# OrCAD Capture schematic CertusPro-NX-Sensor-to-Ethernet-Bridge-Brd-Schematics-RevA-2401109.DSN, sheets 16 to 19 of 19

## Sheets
16 Clock Synthesizer For Camera: size B
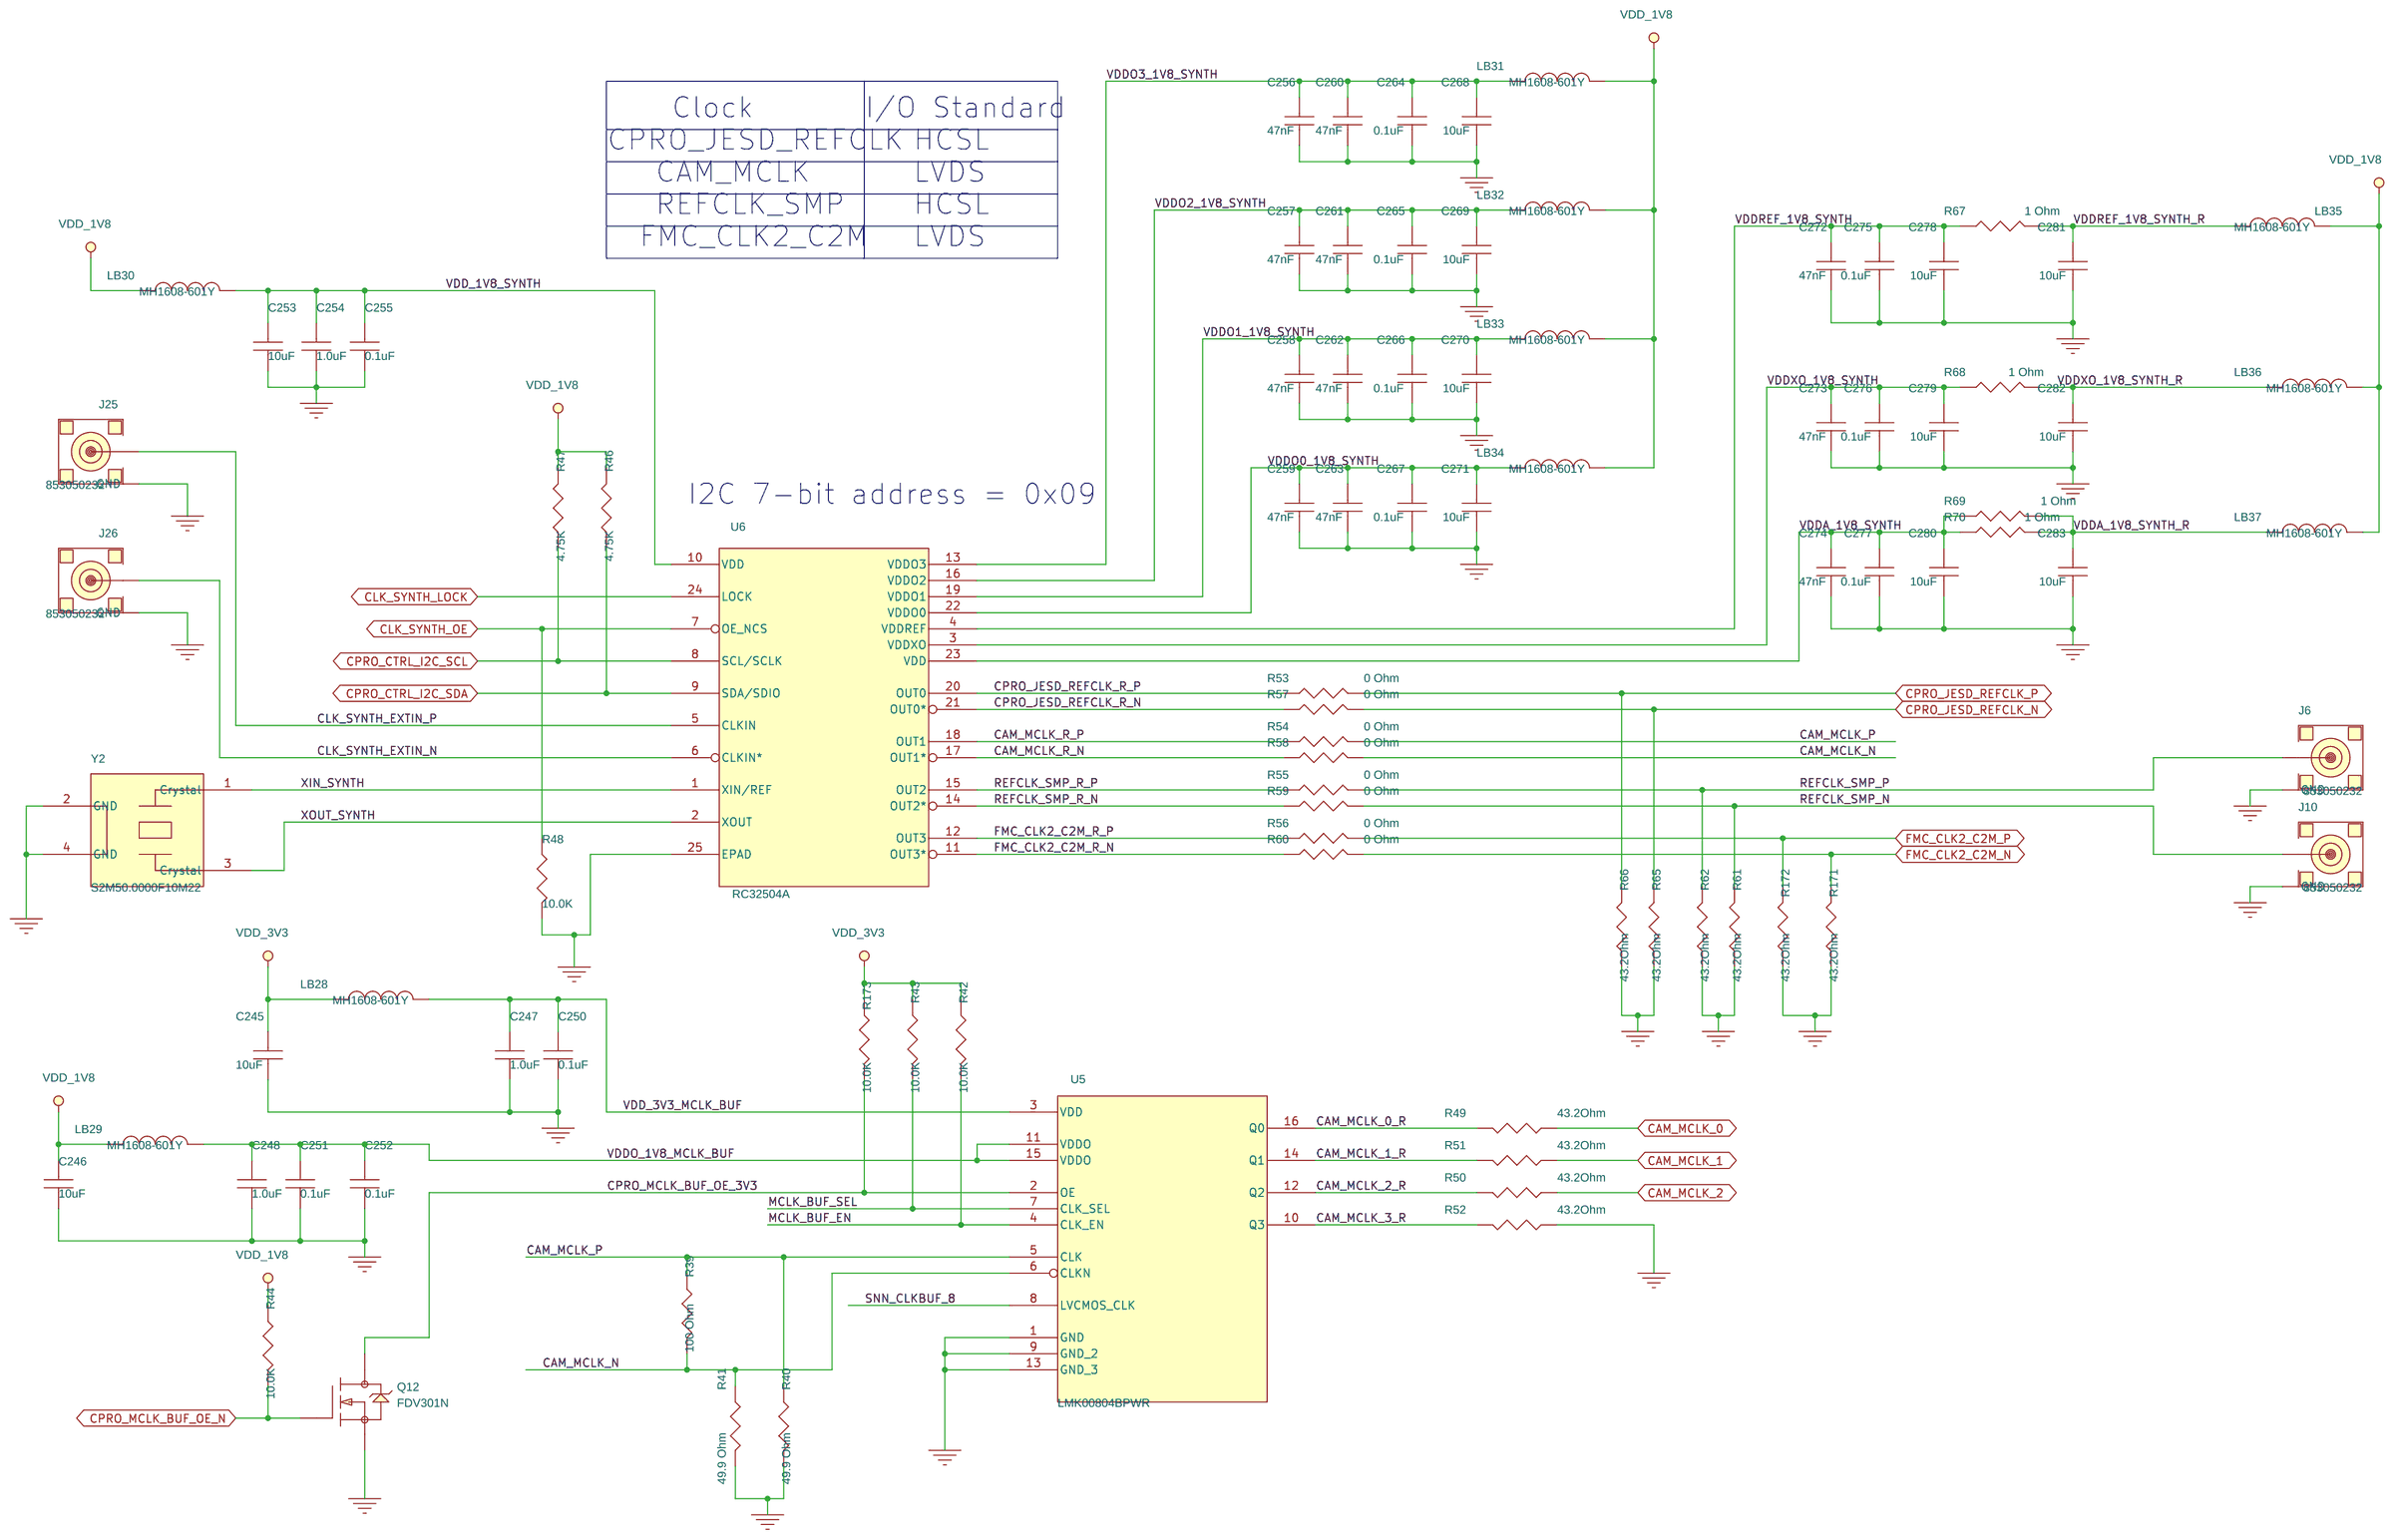
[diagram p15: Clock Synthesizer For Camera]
17 JTAG CHAIN: size C
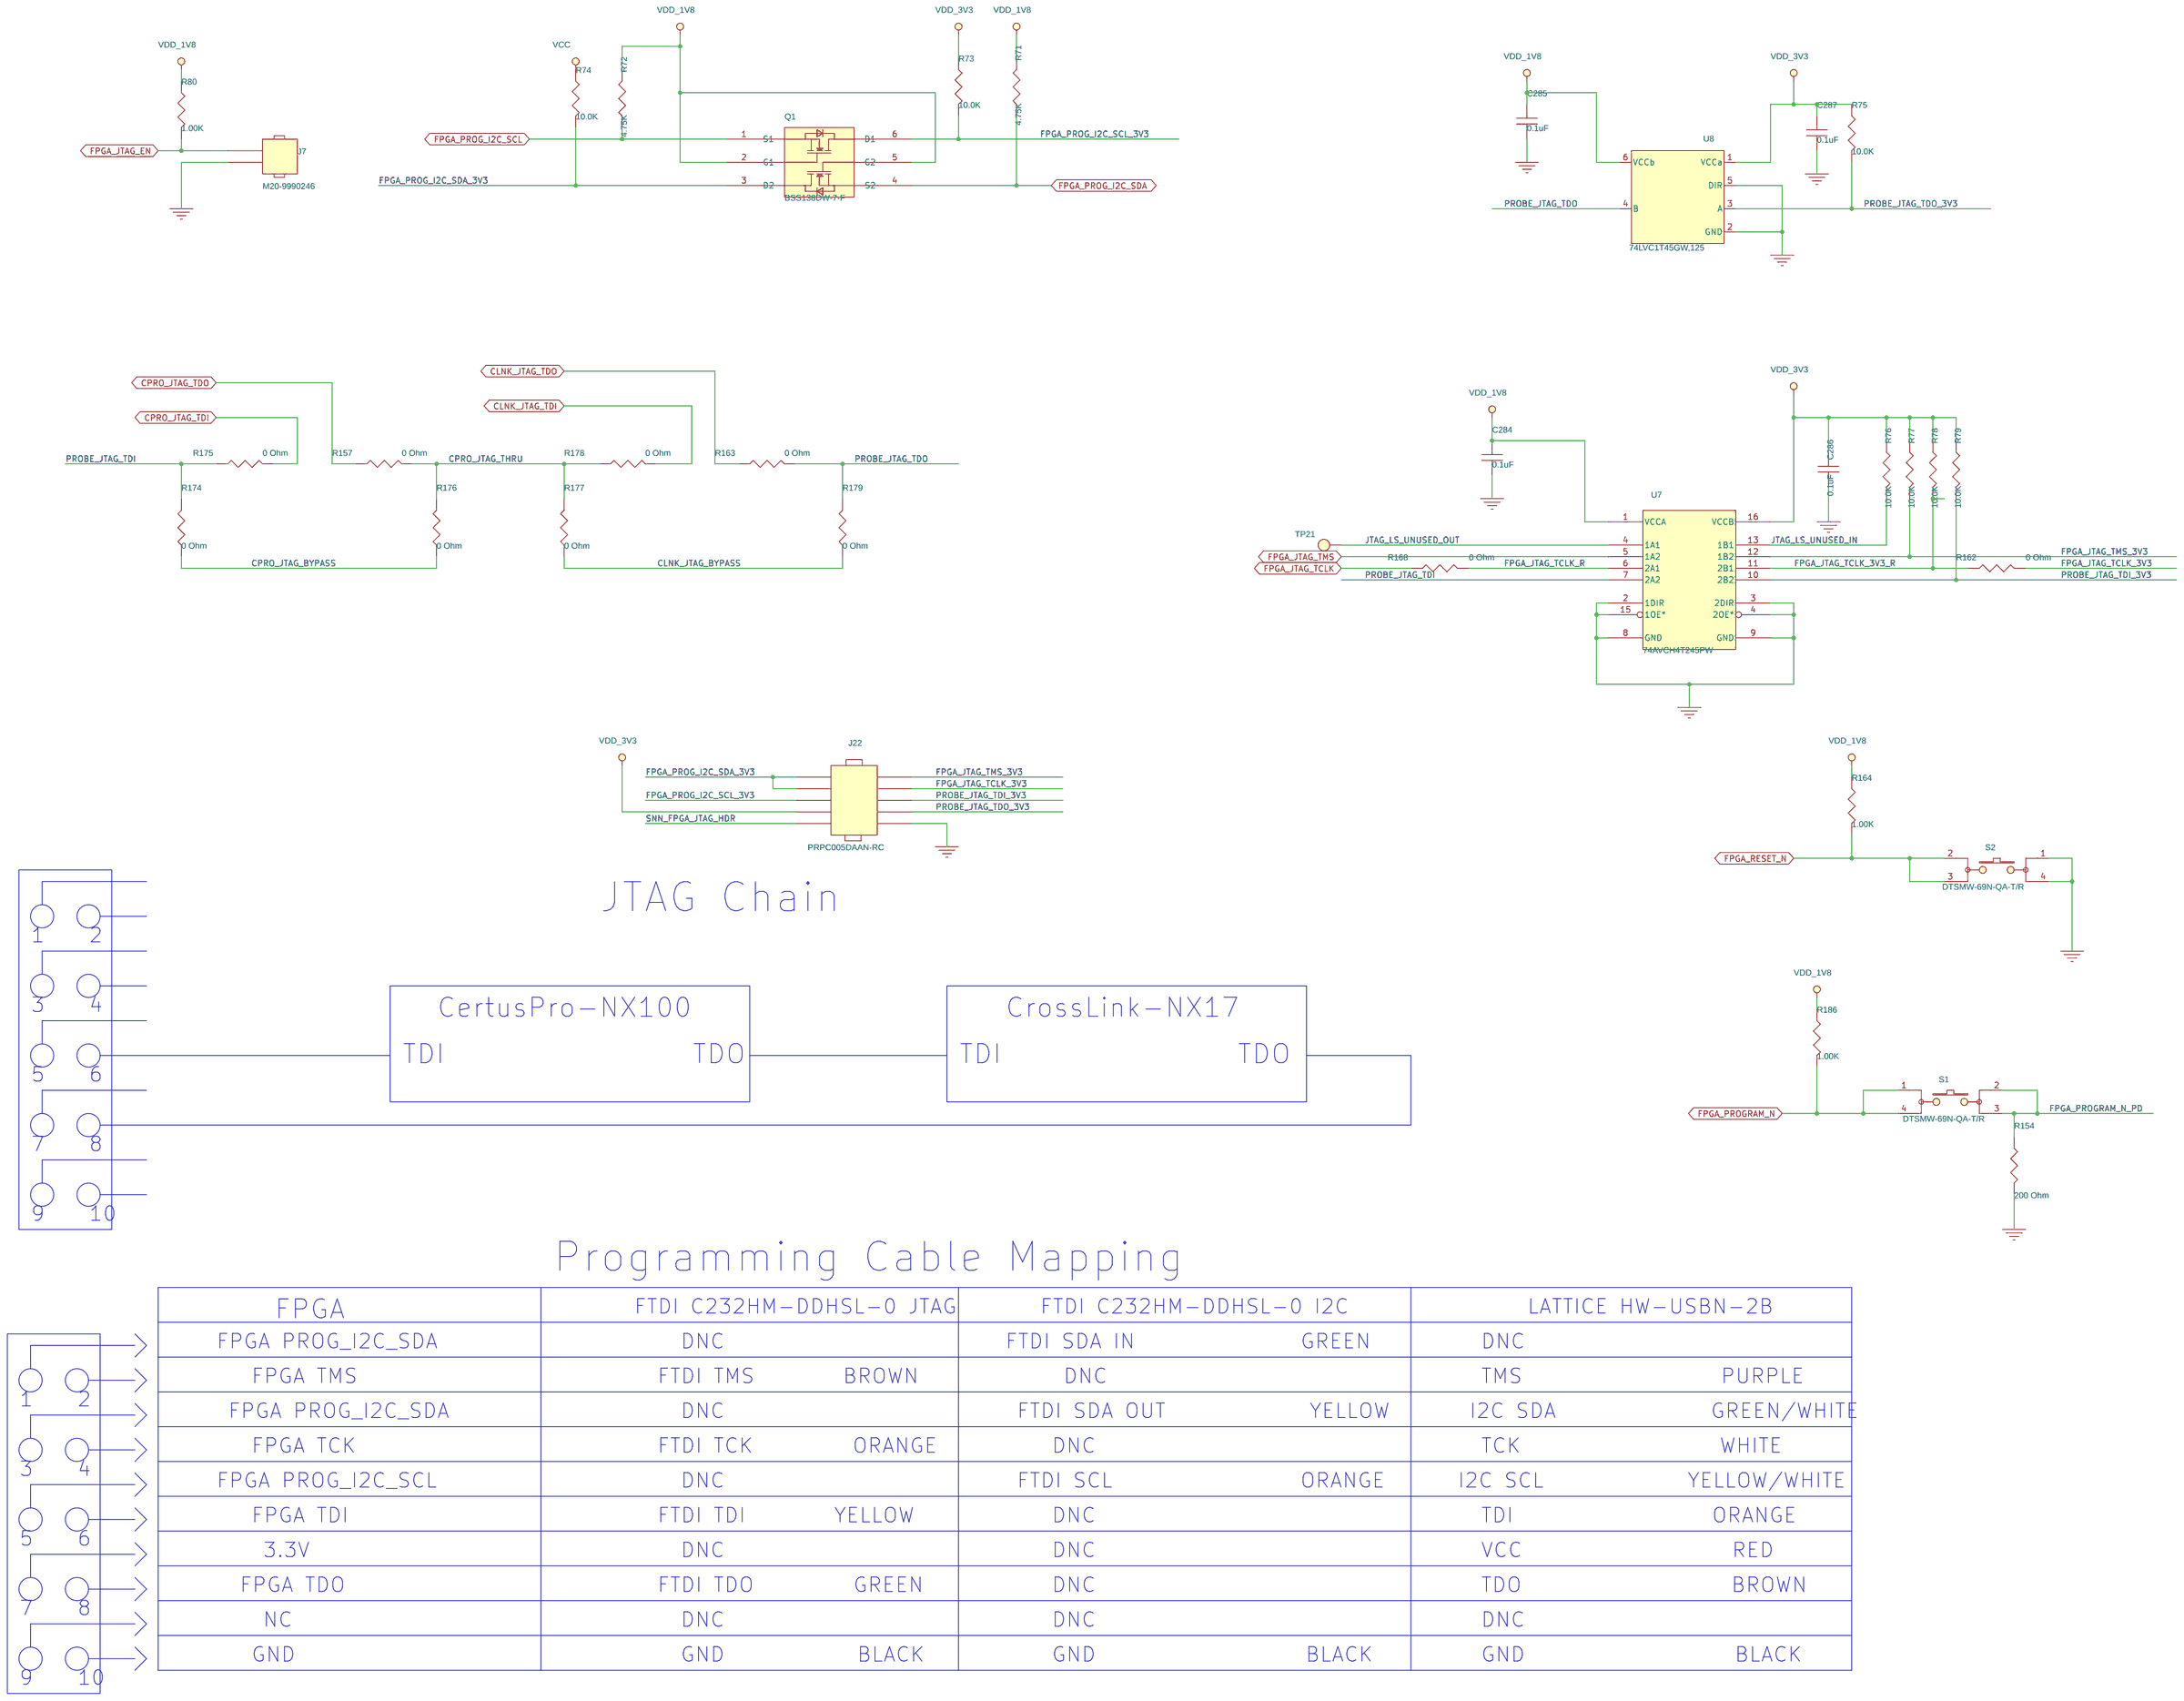
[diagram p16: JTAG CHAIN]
18 Voltage SW Regulator: size B
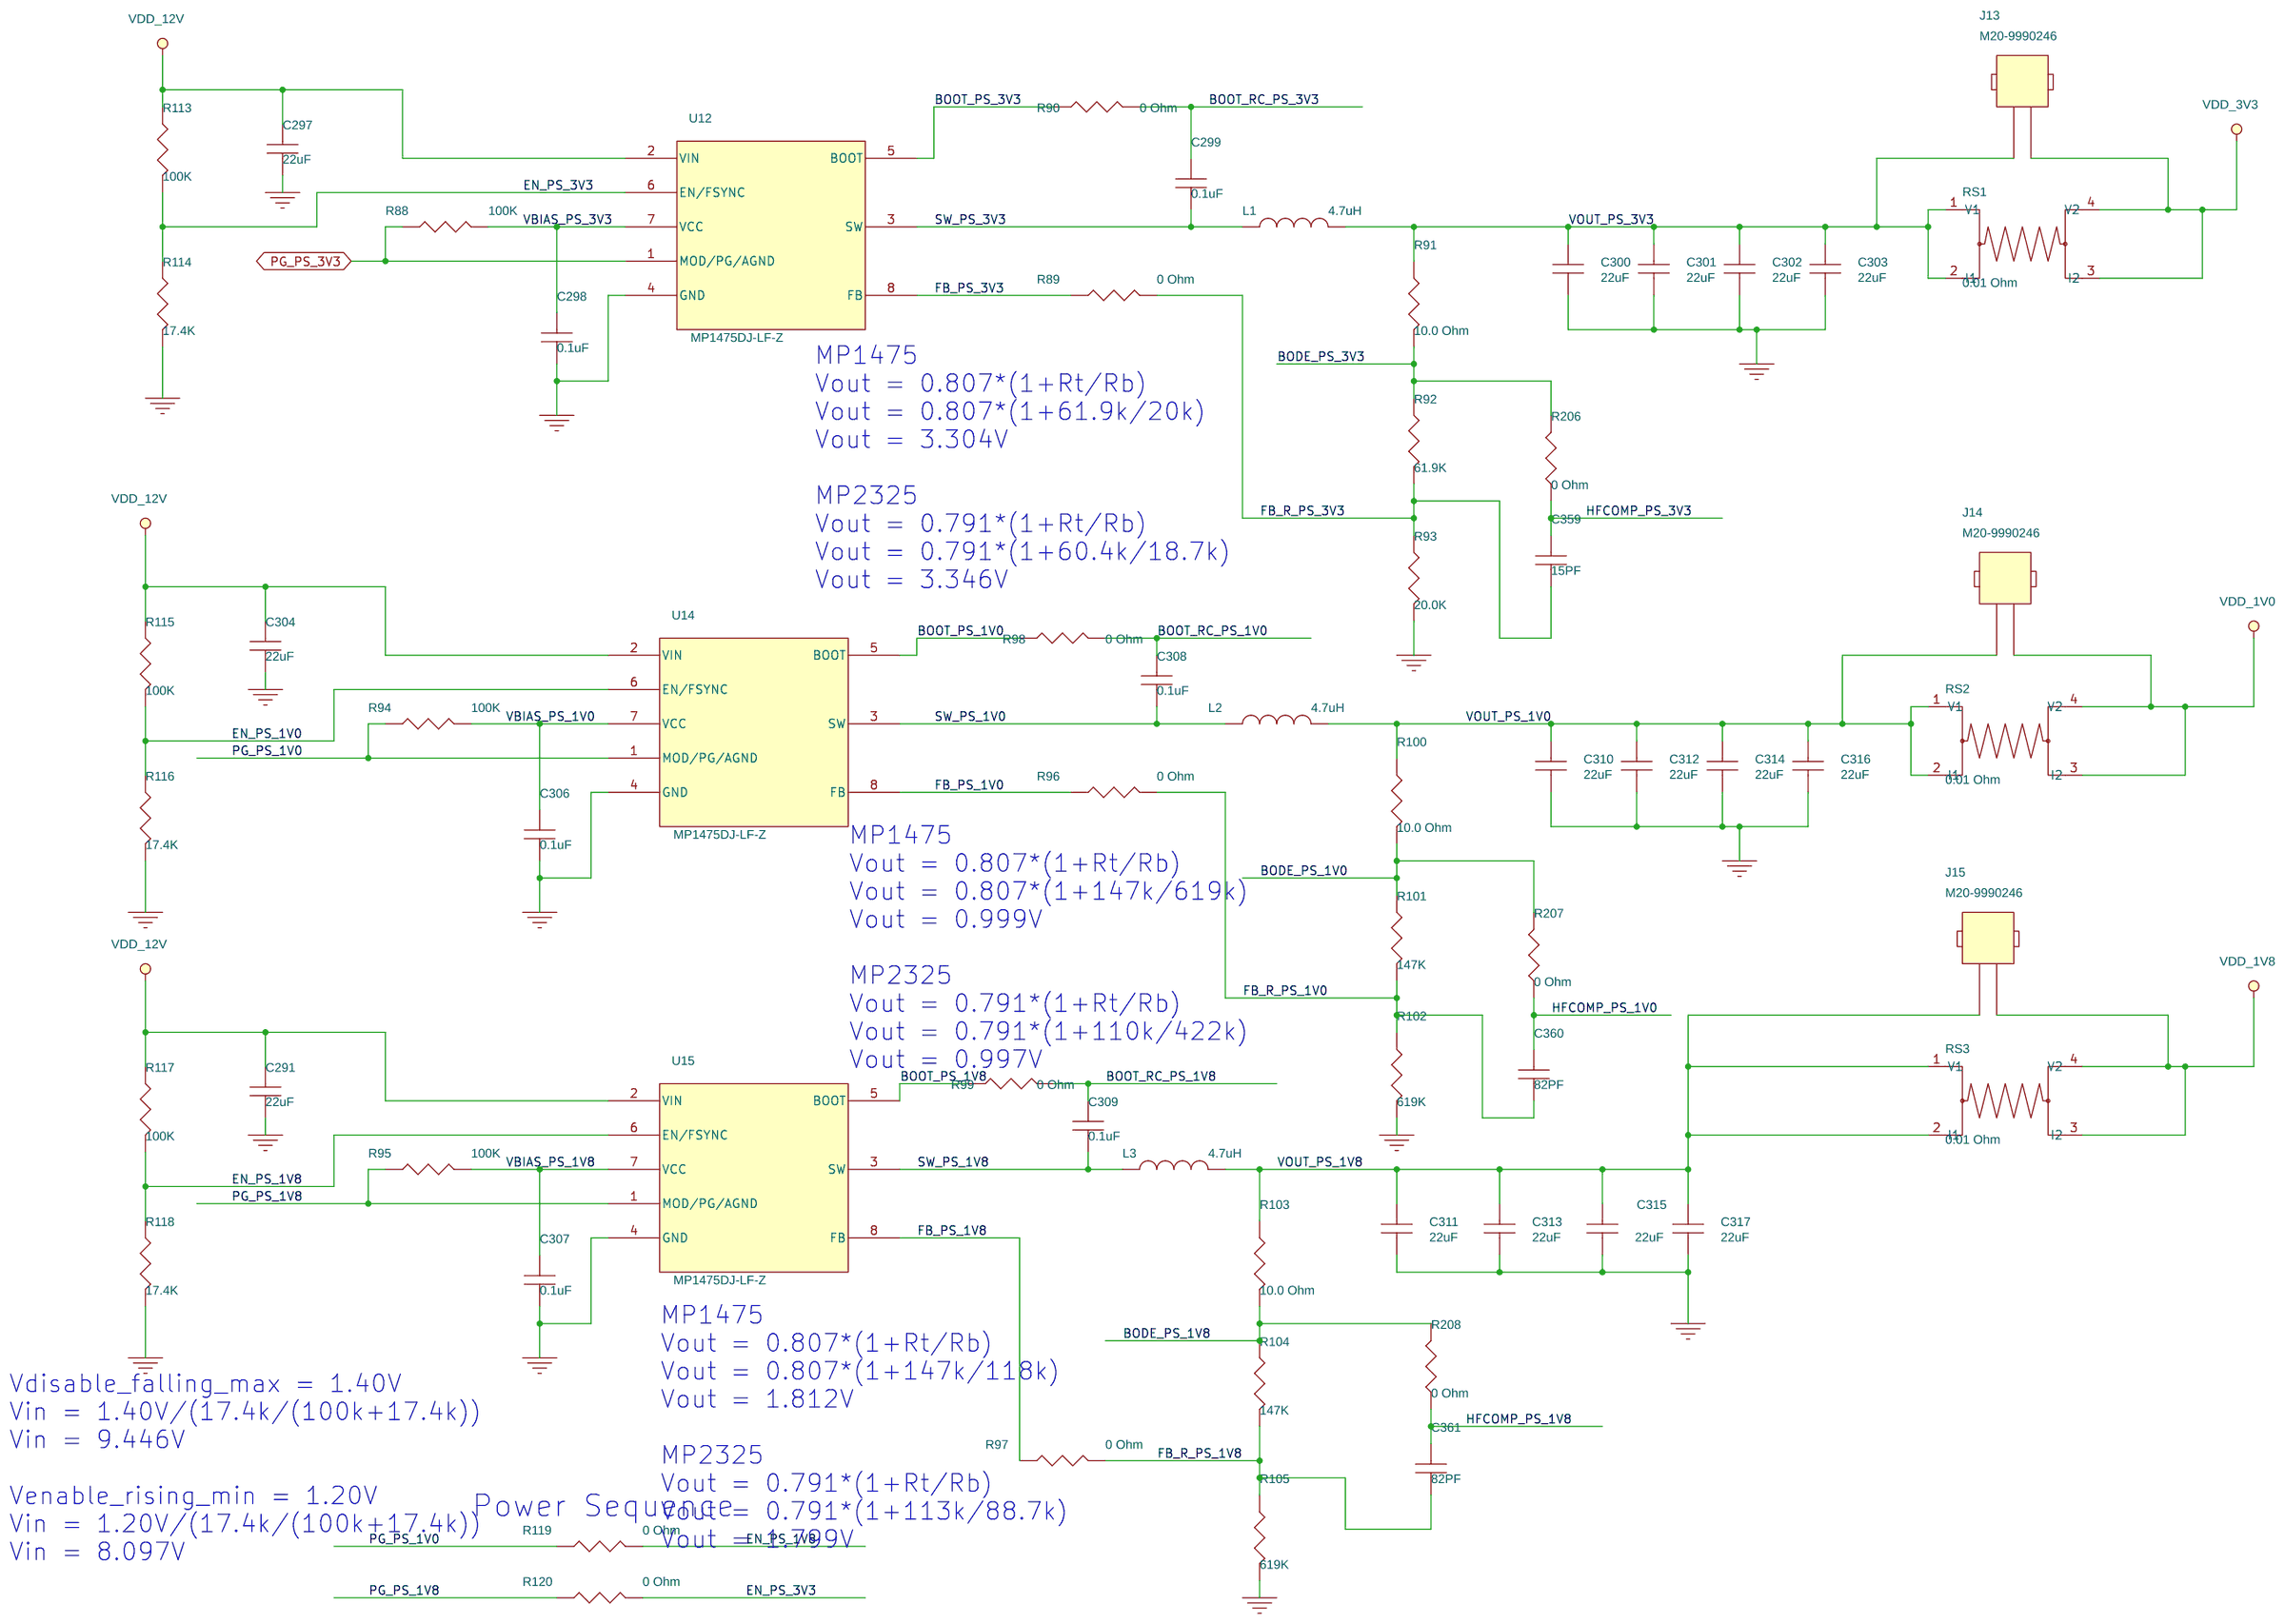
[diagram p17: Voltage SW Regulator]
19 USB Connector and LDOs: size C
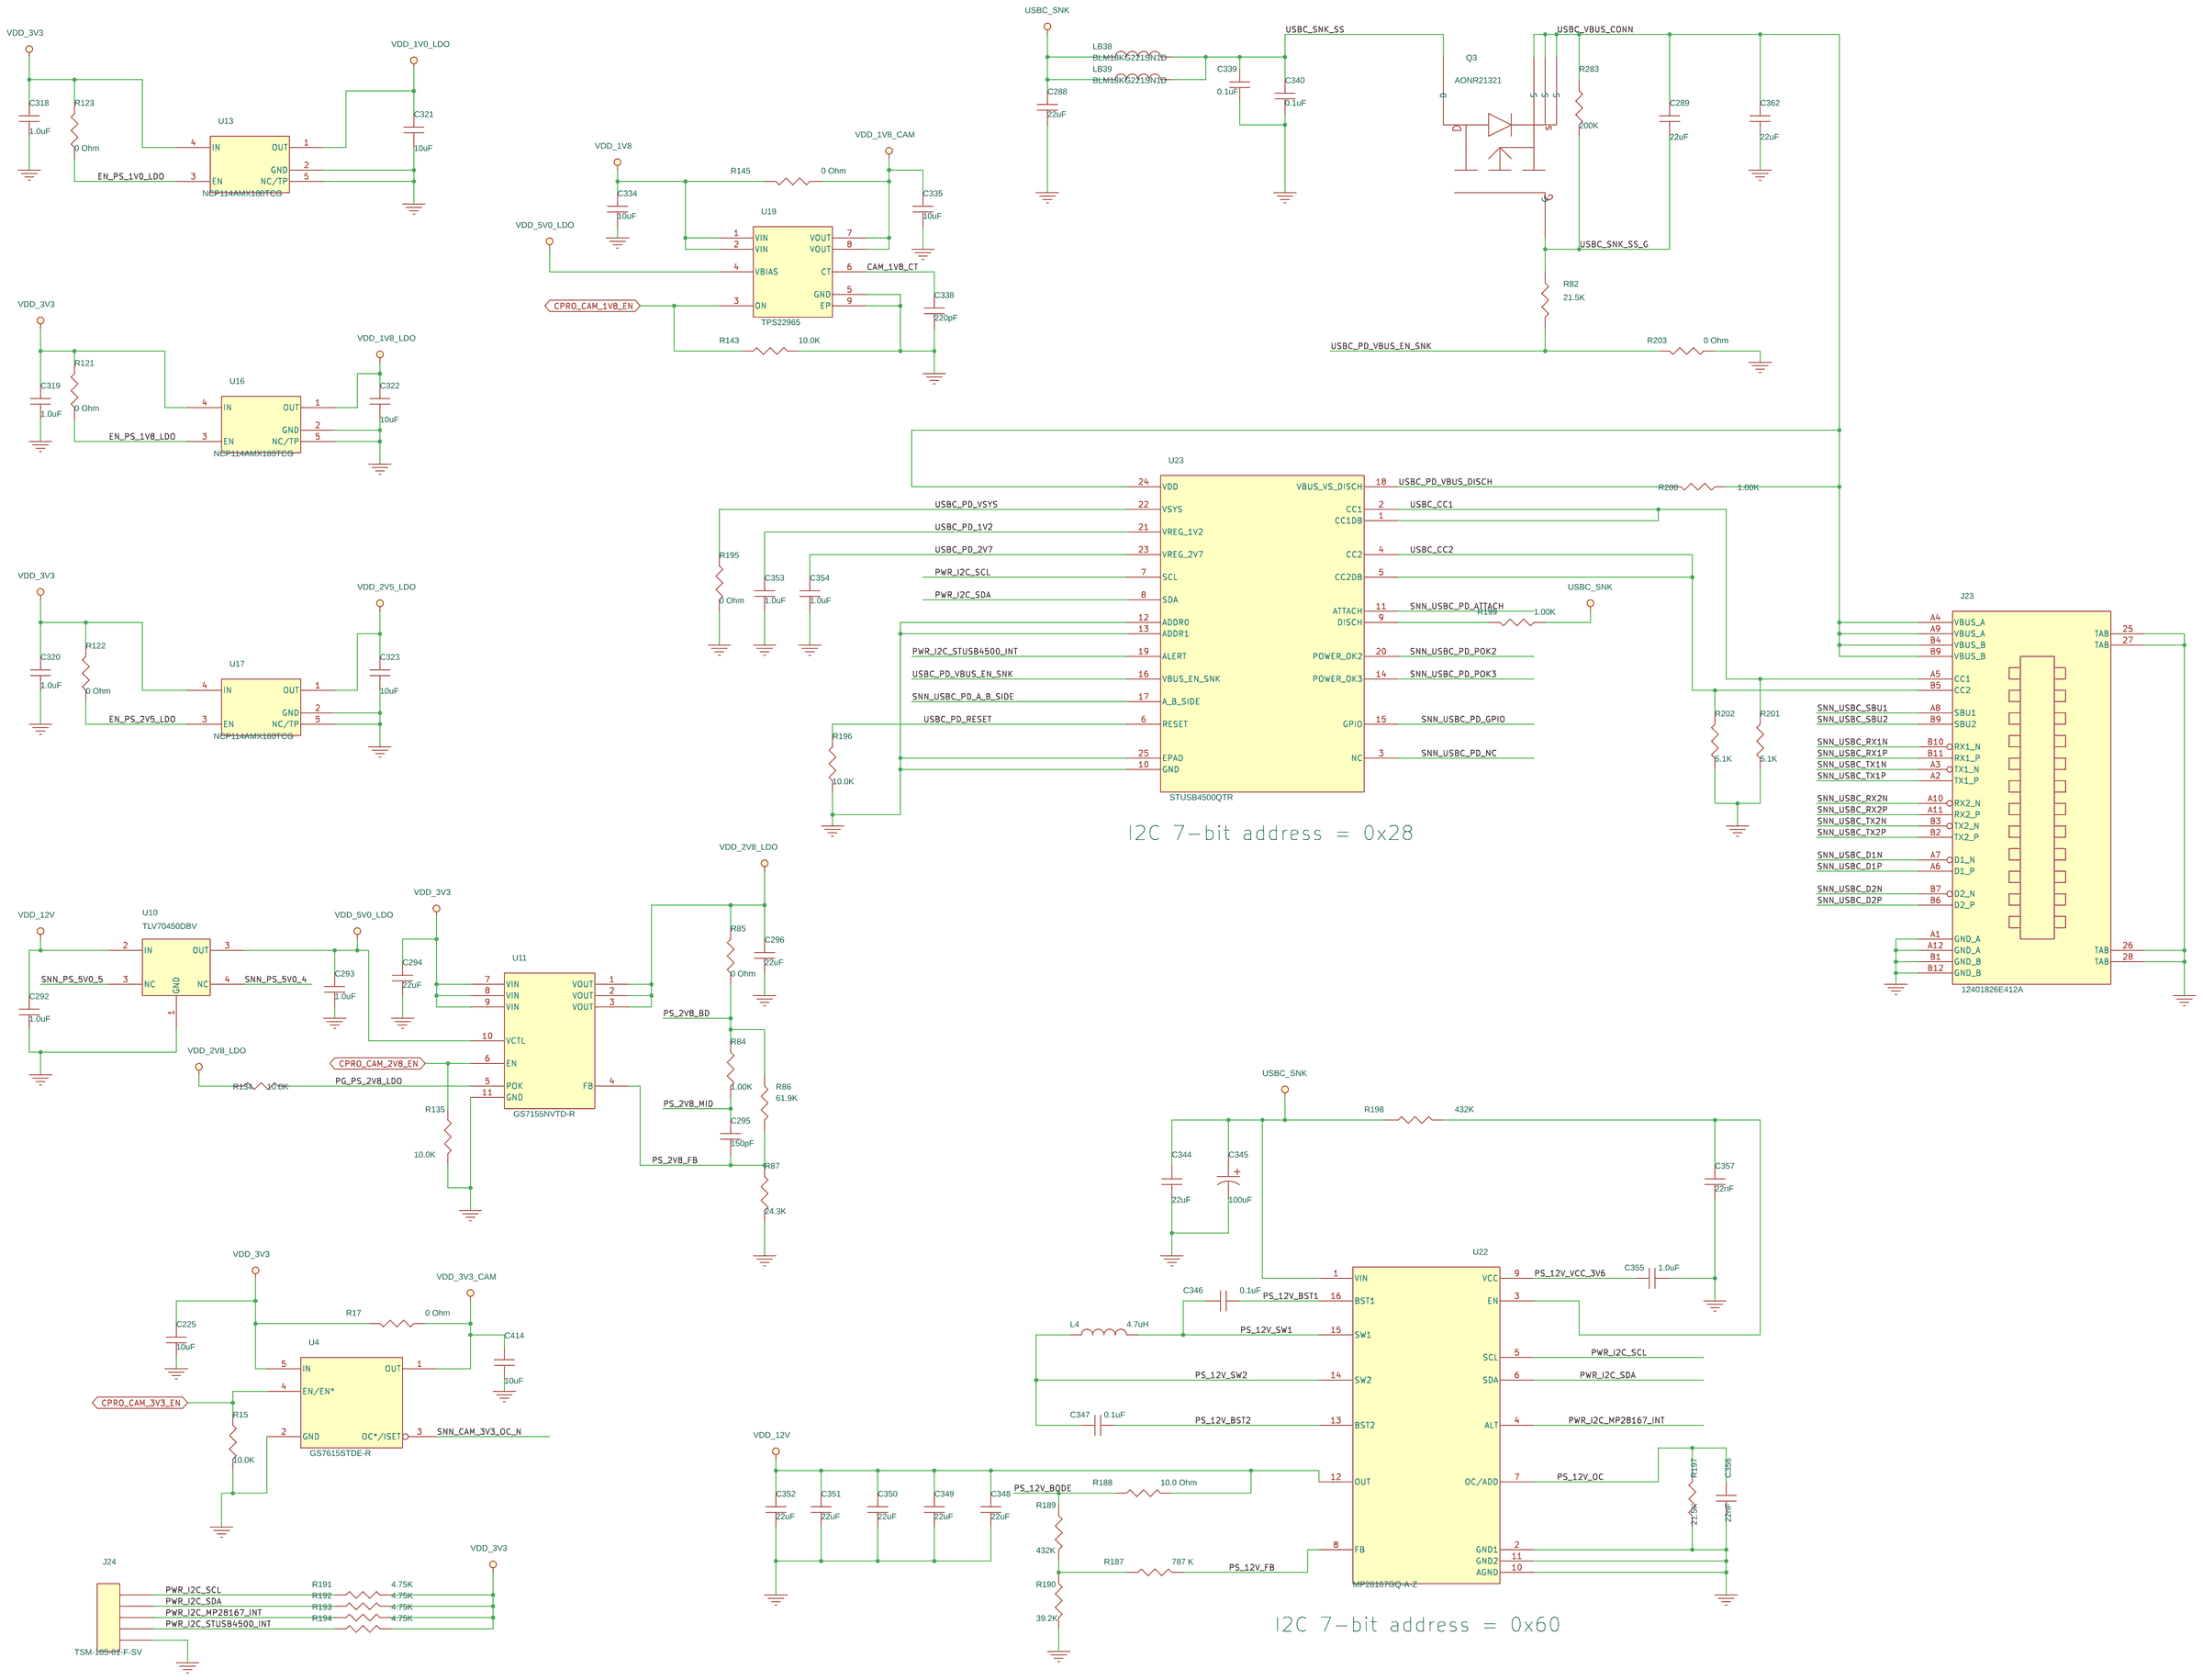
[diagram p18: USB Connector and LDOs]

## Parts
sheet Clock Synthesizer For Camera
C245  10uF  [C0603-L]
C246  10uF  [C0603-L]
C247  1.0uF  [C0402-L]
C248  1.0uF  [C0402-L]
C250  0.1uF  [C0402-L]
C251  0.1uF  [C0402-L]
C252  0.1uF  [C0402-L]
C253  10uF  [C0603-L]
C254  1.0uF  [C0402-L]
C255  0.1uF  [C0402-L]
C256  47nF  [C0201-L]
C257  47nF  [C0201-L]
C258  47nF  [C0201-L]
C259  47nF  [C0201-L]
C260  47nF  [C0201-L]
C261  47nF  [C0201-L]
C262  47nF  [C0201-L]
C263  47nF  [C0201-L]
C264  0.1uF  [C0402-L]
C265  0.1uF  [C0402-L]
C266  0.1uF  [C0402-L]
C267  0.1uF  [C0402-L]
C268  10uF  [C0603-L]
C269  10uF  [C0603-L]
C270  10uF  [C0603-L]
C271  10uF  [C0603-L]
C272  47nF  [C0201-L]
C273  47nF  [C0201-L]
C274  47nF  [C0201-L]
C275  0.1uF  [C0402-L]
C276  0.1uF  [C0402-L]
C277  0.1uF  [C0402-L]
C278  10uF  [C0603-L]
C279  10uF  [C0603-L]
C280  10uF  [C0603-L]
C281  10uF  [C0603-L]
C282  10uF  [C0603-L]
C283  10uF  [C0603-L]
J6  853050232  [SMA]
J10  853050232  [SMA]
J25  853050232  [SMA]
J26  853050232  [SMA]
LB28  MH1608-601Y
LB29  MH1608-601Y
LB30  MH1608-601Y
LB31  MH1608-601Y
LB32  MH1608-601Y
LB33  MH1608-601Y
LB34  MH1608-601Y
LB35  MH1608-601Y
LB36  MH1608-601Y
LB37  MH1608-601Y
Q12  FDV301N
R39  100 Ohm  [R0402-L]
R40  49.9 Ohm  [R0402-L]
R41  49.9 Ohm  [R0402-L]
R42  10.0K  [R0402-L]
R43  10.0K  [R0402-L]
R44  10.0K  [R0402-L]
R46  4.75K  [R0402-L]
R47  4.75K  [R0402-L]
R48  10.0K  [R0402-L]
R49  43.2Ohm  [R0402-L]
R50  43.2Ohm  [R0402-L]
R51  43.2Ohm  [R0402-L]
R52  43.2Ohm  [R0402-L]
R53  0 Ohm  [R0402-L]
R54  0 Ohm  [R0402-L]
R55  0 Ohm  [R0402-L]
R56  0 Ohm  [R0402-L]
R57  0 Ohm  [R0402-L]
R58  0 Ohm  [R0402-L]
R59  0 Ohm  [R0402-L]
R60  0 Ohm  [R0402-L]
R61  43.2Ohm  [R0402-L]
R62  43.2Ohm  [R0402-L]
R65  43.2Ohm  [R0402-L]
R66  43.2Ohm  [R0402-L]
R67  1 Ohm  [R0402-L]
R68  1 Ohm  [R0402-L]
R69  1 Ohm  [R0402-L]
R70  1 Ohm  [R0402-L]
R171  43.2Ohm  [R0402-L]
R172  43.2Ohm  [R0402-L]
R173  10.0K  [R0402-L]
U5  LMK00804BPWR  [PW16_TEX]
U6  RC32504A
Y2  S2M50.0000F10M22
sheet JTAG CHAIN
C284  0.1uF  [C0402-L]
C285  0.1uF  [C0402-L]
C286  0.1uF  [C0402-L]
C287  0.1uF  [C0402-L]
J7  M20-9990246  [CONN2_M20-999_1x2_HRW]
J22  PRPC005DAAN-RC  [CON10_2X5_TU_TSW_SAI]
Q1  BSS138DW-7-F  [SOT363_DIO]
R71  4.75K  [R0402-L]
R72  4.75K  [R0402-L]
R73  10.0K  [R0402-L]
R74  10.0K  [R0402-L]
R75  10.0K  [R0402-L]
R76  10.0K  [R0402-L]
R77  10.0K  [R0402-L]
R78  10.0K  [R0402-L]
R79  10.0K  [R0402-L]
R80  1.00K  [R0402-L]
R154  200 Ohm  [R0402-L]
R157  0 Ohm  [R0402-L]
R162  0 Ohm  [R0402-L]
R163  0 Ohm  [R0402-L]
R164  1.00K  [R0402-L]
R168  0 Ohm  [R0402-L]
R174  0 Ohm  [R0402-L]
R175  0 Ohm  [R0402-L]
R176  0 Ohm  [R0402-L]
R177  0 Ohm  [R0402-L]
R178  0 Ohm  [R0402-L]
R179  0 Ohm  [R0402-L]
R186  1.00K  [R0402-L]
S1  DTSMW-69N-QA-T/R
S2  DTSMW-69N-QA-T/R
TP21  TP1  [TPd39c60]
U7  74AVCH4T245PW
U8  74LVC1T45GW,125  [TSSOP6_SOT363-2_NEX]
sheet USB Connector and LDOs
C225  10uF  [C0603-L]
C288  22uF  [C0805]
C289  22uF  [C0805]
C292  1.0uF  [C0402-L]
C293  1.0uF  [C0402-L]
C294  22uF  [C0805]
C295  150pF  [C0402-L]
C296  22uF  [C0805]
C318  1.0uF  [C0402-L]
C319  1.0uF  [C0402-L]
C320  1.0uF  [C0402-L]
C321  10uF  [C0603-L]
C322  10uF  [C0603-L]
C323  10uF  [C0603-L]
C334  10uF  [C0603-L]
C335  10uF  [C0603-L]
C338  220pF  [C0402-L]
C339  0.1uF  [C0402-L]
C340  0.1uF  [C0402-L]
C344  22uF  [C0805]
C345  100uF
C346  0.1uF  [C0402-L]
C347  0.1uF  [C0402-L]
C348  22uF  [C0805]
C349  22uF  [C0805]
C350  22uF  [C0805]
C351  22uF  [C0805]
C352  22uF  [C0805]
C353  1.0uF  [C0402-L]
C354  1.0uF  [C0402-L]
C355  1.0uF  [C0402-L]
C356  22nF  [C0402-L]
C357  22nF  [C0402-L]
C362  22uF  [C0805]
C414  10uF  [C0603-L]
J23  12401826E412A
J24  TSM-105-01-F-SV
L4  4.7uH
LB38  BLM18KG221SN1D
LB39  BLM18KG221SN1D
Q3  AONR21321
R15  10.0K  [R0402-L]
R17  0 Ohm  [R0402-L]
R82  21.5K  [R0402-L]
R84  1.00K  [R0402-L]
R85  0 Ohm  [R0402-L]
R86  61.9K  [R0402-L]
R87  24.3K  [R0402-L]
R121  0 Ohm  [R0402-L]
R122  0 Ohm  [R0402-L]
R123  0 Ohm  [R0402-L]
R134  10.0K  [R0402-L]
R135  10.0K  [R0402-L]
R143  10.0K  [R0402-L]
R145  0 Ohm  [R0402-L]
R187  787 K  [R0402-L]
R188  10.0 Ohm  [R0402-L]
R189  432K  [R0402-L]
R190  39.2K  [R0402-L]
R191  4.75K  [R0402-L]
R192  4.75K  [R0402-L]
R193  4.75K  [R0402-L]
R194  4.75K  [R0402-L]
R195  0 Ohm  [R0402-L]
R196  10.0K  [R0402-L]
R197  21.5K  [R0402-L]
R198  432K  [R0402-L]
R199  1.00K  [R0402-L]
R200  1.00K  [R0402-L]
R201  5.1K  [R0402-L]
R202  5.1K  [R0402-L]
R203  0 Ohm  [R0402-L]
R283  200K  [R0402-L]
U4  GS7615STDE-R
U10  TLV70450DBV
U11  GS7155NVTD-R
U13  NCP114AMX180TCG
U16  NCP114AMX180TCG
U17  NCP114AMX180TCG
U19  TPS22965
U22  MP28167GQ-A-Z
U23  STUSB4500QTR
sheet Voltage SW Regulator
C291  22uF  [C0805]
C297  22uF  [C0805]
C298  0.1uF  [C0402-L]
C299  0.1uF  [C0402-L]
C300  22uF  [C0603-L]
C301  22uF  [C0603-L]
C302  22uF  [C0603-L]
C303  22uF  [C0603-L]
C304  22uF  [C0805]
C306  0.1uF  [C0402-L]
C307  0.1uF  [C0402-L]
C308  0.1uF  [C0402-L]
C309  0.1uF  [C0402-L]
C310  22uF  [C0603-L]
C311  22uF  [C0603-L]
C312  22uF  [C0603-L]
C313  22uF  [C0603-L]
C314  22uF  [C0603-L]
C315  22uF  [C0603-L]
C316  22uF  [C0603-L]
C317  22uF  [C0603-L]
C359  15PF  [C0402-L]
C360  82PF  [C0402-L]
C361  82PF  [C0402-L]
J13  M20-9990246  [CONN2_M20-999_1x2_HRW]
J14  M20-9990246  [CONN2_M20-999_1x2_HRW]
J15  M20-9990246  [CONN2_M20-999_1x2_HRW]
L1  4.7uH
L2  4.7uH
L3  4.7uH
R88  100K  [R0402-L]
R89  0 Ohm  [R0402-L]
R90  0 Ohm  [R0402-L]
R91  10.0 Ohm  [R0402-L]
R92  61.9K  [R0402-L]
R93  20.0K  [R0402-L]
R94  100K  [R0402-L]
R95  100K  [R0402-L]
R96  0 Ohm  [R0402-L]
R97  0 Ohm  [R0402-L]
R98  0 Ohm  [R0402-L]
R99  0 Ohm  [R0402-L]
R100  10.0 Ohm  [R0402-L]
R101  147K  [R0402-L]
R102  619K  [R0402-L]
R103  10.0 Ohm  [R0402-L]
R104  147K  [R0402-L]
R105  619K  [R0402-L]
R113  100K  [R0402-L]
R114  17.4K  [R0402-L]
R115  100K  [R0402-L]
R116  17.4K  [R0402-L]
R117  100K  [R0402-L]
R118  17.4K  [R0402-L]
R119  0 Ohm  [R0402-L]
R120  0 Ohm  [R0402-L]
R206  0 Ohm  [R0402-L]
R207  0 Ohm  [R0402-L]
R208  0 Ohm  [R0402-L]
RS1  0.01 Ohm
RS2  0.01 Ohm
RS3  0.01 Ohm
U12  MP1475DJ-LF-Z
U14  MP1475DJ-LF-Z
U15  MP1475DJ-LF-Z

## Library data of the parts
C225 C245 C246 C253 C268-C271 C278-C283 C321-C323 C334 C335 C414 = CAP_NP: 10 µF ±10% 25V Ceramic Capacitor X5R 0603 (1608 Metric); Manufacturer: Murata; Manufacturer Part Number: GRM188R61E106KA73J; Part Number: GRM188R61E106KA73J; Part type: Ceramic; Tolerance: 10%; Voltage: 25V; Datasheet: https://search.murata.co.jp/Ceramy/image/img/A01X/G101/ENG/GRM188R61E106KA73-01A.pdf
C247 C248 C254 C292 C293 C318-C320 C353-C355 = CAP_NP: 1 µF ±10% 25V Ceramic Capacitor X5R 0402 (1005 Metric); Manufacturer: Murata; Manufacturer Part Number: GRM155R61E105KA12D; Part Number: GRM155R61E105KA12D; Part type: Ceramic; Tolerance: 10%; Voltage: 25V; Datasheet: https://www.digikey.com/en/htmldatasheets/production/2354729/0/0/1/grm155r61e105ka12x-ref-sheet.html?site=US&lang=en&cur=USD
C250-C252 C255 C264-C267 C275-C277 C284-C287 C339 C340 = CAP_NP: 0.1 µF ±10% 50V Ceramic Capacitor X7R 0402 (1005 Metric); Manufacturer: Murata; Manufacturer Part Number: GRM155R71H104KE14J; Part Number: GRM155R71H104KE14J; Part type: Ceramic; Tolerance: 10%; Voltage: 50V; Datasheet: https://search.murata.co.jp/Ceramy/image/img/A01X/G101/ENG/GRM155R71H104KE14-01.pdf
C256-C263 C272-C274 = CAP_NP: 0.047 µF ±10% 10V Ceramic Capacitor X6S 0201 (0603 Metric); Manufacturer: Murata; Manufacturer Part Number: GRM033C81A473KE05D; Part Number: GRM033C81A473KE05D; Part type: Ceramic; Tolerance: 10%; Voltage: 10v; Datasheet: https://search.murata.co.jp/Ceramy/image/img/A01X/G101/ENG/GRM033C81A473KE05-01.pdf
J6 J10 J25 J26 = SMP-PLUG: CONN SMP PLUG STR 50 OHM SMD; Manufacturer: Molex; Part Type: Connector; Datasheet: https://www.molex.com/en-us/products/part-detail/853050232?display=pdf
LB28-LB37 = LB_Inductor: FERRITE BEAD BEAD_0603 Ferrite 600ohm 25% 200mohm 0.8A; Current: 0.8A; DCR: 200mohm; Manufacturer: Bourns, Inc.
Q12 = N-MOS: MOSFET N-CH 25V 220MA SOT23; Manufacturer: ON Semiconductor Corporation; Part Type: MOSFET N-CH; Datasheet: https://www.onsemi.com/pdf/datasheet/fdv301n-d.pdf
R39 = R: 100 Ohms ±1% 0.063W, 1/16W Chip Resistor 0402 (1005 Metric) Thick Film; Manufacturer: Yageo; Manufacturer Part Number: RC0402FR-07100KP; Part Number: RC0402FR-07100KP; Part type: Thick Film; Power: 1/16W; Tolerance: 1%; Datasheet: https://www.yageo.com/upload/media/product/productsearch/datasheet/rchip/PYu-RC_Group_51_RoHS_L_12.pdf
R40 R41 = R: 49.9 Ohms ±1% 0.063W, 1/16W Chip Resistor 0402 (1005 Metric) Moisture Resistant Thick Film; Manufacturer: Yageo; Manufacturer Part Number: RC0402FR-0749R9L; Part Number: RC0402FR-0749R9L; Part type: Thick Film; Power: 1/16W; Tolerance: 1%; Datasheet: https://www.yageo.com/upload/media/product/app/datasheet/rchip/pyu-rc_group_51_rohs_l.pdf
R15 R42-R44 R48 R73-R79 R134 R135 R143 R173 R196 = R: 10 kOhms ±1% 0.063W, 1/16W Chip Resistor 0402 (1005 Metric) Thick Film; Manufacturer: Yageo; Manufacturer Part Number: RC0402FR-0710KP; Part Number: RC0402FR-0710KP; Part type: Thick Film; Power: 1/16W; Tolerance: 1%; Datasheet: https://www.yageo.com/upload/media/product/products/datasheet/rchip/PYu-RC_51_RoHS_P_4.pdf
R46 R47 R71 R72 R191-R194 = R: RES 0402 4.75kohm 1% 62.5mW; Manufacturer: Matsushita Electric Works, Ltd.; Manufacturer Part Number: ERJ2RKF4751X; Part Number: ERJ2RKF4751X; Part type: Thick Film; Power: 62.5mW; Tolerance: 1%
R49-R52 R61 R62 R65 R66 R171 R172 = R: RES 0402 43.2ohm 1% 62.5mW; Manufacturer: Vishay Americas Inc.; Manufacturer Part Number: CRCW040243R2FKED; Part Number: CRCW040243R2FKED; Part type: Thick Film; Power: 62.5mW; Tolerance: 1%
R17 R53-R60 R85 R89 R90 R96-R99 R119-R123 R145 R157 R162 R163 R168 R174-R179 R195 R203 R206-R208 = R: 0 Ohms Jumper Chip Resistor 0402 (1005 Metric) Moisture Resistant Thick Film; Manufacturer: Yageo; Manufacturer Part Number: RC0402FR-070RL; Part Number: RC0402FR-070RL; Part type: Thick Film; Datasheet: https://www.yageo.com/upload/media/product/productsearch/datasheet/rchip/PYu-RC_Group_51_RoHS_L_12.pdf
R67-R70 = R: 1 Ohms ±1% 0.063W, 1/16W Chip Resistor 0402 (1005 Metric) Moisture Resistant Thick Film; Manufacturer: Yageo; Manufacturer Part Number: RC0402FR-071RL; Part Number: RC0402FR-071RL; Part type: Thick Film; Datasheet: https://www.yageo.com/upload/media/product/products/datasheet/rchip/PYu-RC_Group_51_RoHS_L_12.pdf
U5 = LMK00804B: Clock Fanout Buffer (Distribution), Multiplexer IC 1:4 350 MHz 16-TSSOP (0.173", 4.40mm Width); Manufacturer: Texas Instruments, Inc.; Datasheet: https://www.ti.com/lit/ds/symlink/lmk00804b.pdf?ts=1728895449355&ref_url=https%253A%252F%252Fwww.ti.com%252Fproduct%252FLMK00804B%252Fpart-details%252FLMK00804BPWR
U6 = RC32504A: Frequency Translator IC 180MHz, 1GHz 1 24-WFQFN Exposed Pad; Manufacturer: Renesas Electronics Corporation; Manufacturer Part Number: RC32504A000GNK#BB0; Part Number: RC32504A000GNK#BB0
Y2 = S2M50_0: XTAL SMD_25X20 50MHz 20ppm Fundamental 10pF S2M50.0000F10M22; Manufacturer: Nakagawa Electronics Limited; Part Type: Crystal
J7 J13-J15 = HEADER_2: Connector Header Through Hole 2 position 0.100" (2.54mm); Manufacturer: Harwin; Part Type: Connector; Datasheet: https://cdn.harwin.com/pdfs/C001XX_M20_Series_Connectors.pdf
J22 = HEADER_5X2: Connector Header Through Hole 10 position 0.100" (2.54mm); Manufacturer: Sullins; Part Type: Connector; Datasheet: https://drawings-pdf.s3.amazonaws.com/11636.pdf
Q1 = BSS138DW-7: MOSFET 2N-CH 50V 0.2A SOT363; Manufacturer: Diodes Incorporated; Part Type: MOSFET N-CH; Datasheet: https://www.diodes.com/assets/Datasheets/ds30203.pdf
R80 R84 R164 R186 R199 R200 = R: 1 kOhms ±1% 0.063W, 1/16W Chip Resistor 0402 (1005 Metric) Thick Film; Manufacturer: Yageo; Manufacturer Part Number: RC0402FR-071KP; Part Number: RC0402FR-071KP; Part type: Thick Film; Power: 1/16W; Tolerance: 1%; Datasheet: https://www.yageo.com/upload/media/product/products/datasheet/rchip/PYu-RC_51_RoHS_P_4.pdf
R154 = R: 200 Ohms ±1% 0.063W, 1/16W Chip Resistor 0402 (1005 Metric) Moisture Resistant Thick Film; Manufacturer: Yageo; Manufacturer Part Number: RC0402FR-07200RL; Part Number: RC0402FR-07200RL; Part type: Thick Film; Power: 1/16W; Tolerance: 1%; Datasheet: https://www.yageo.com/upload/media/product/products/datasheet/rchip/PYu-RC_Group_51_RoHS_L_12.pdf
S1 S2 = DTSMW-69N: Tactile Switches 50mA 12VDC 6.2X6.3MM; Manufacturer: Diptronics; Datasheet: https://www.mouser.in/datasheet/2/910/460_DTSGMW-6-1571488.pdf
TP21 = TP1: Test Point 0.39"; Manufacturer: NA; Part Type: Test Point; Datasheet: NA
U7 = 74AVCH4T245PW
U8 = 74LVC1T45: Voltage Level Translator Bidirectional 1 Circuit 1 Channel 420Mbps 6-TSSOP; Manufacturer: Nexperia; Part Type: Level Translator; Datasheet: https://assets.nexperia.com/documents/data-sheet/74LVC_LVCH1T45.pdf
C288 C289 C291 C294 C296 C297 C304 C344 C348-C352 C362 = CAP_NP: 22 µF ±20% 25V Ceramic Capacitor X5R 0805 (2012 Metric); Manufacturer: Murata; Manufacturer Part Number: GRM21BR61E226ME44K; Part Number: GRM21BR61E226ME44K; Part type: Ceramic; Tolerance: 20%; Voltage: 25V; Datasheet: https://search.murata.co.jp/Ceramy/image/img/A01X/G101/ENG/GRM21BR61E226ME44-01.pdf
C295 = CAP_NP: 150 pF ±5% 50V Ceramic Capacitor C0G, NP0 0402 (1005 Metric); Manufacturer: YAGEO; Manufacturer Part Number: CC0402JRNPO9BN151; Part Number: CC0402JRNPO9BN151; Part type: Ceramic; Tolerance: 5%; Voltage: 50V; Datasheet: https://www.yageo.com/upload/media/product/productsearch/datasheet/mlcc/UPY-GP_NP0_16V-to-50V_18.pdf
C338 = CAP_NP: 220 pF ±10% 50V Ceramic Capacitor X7R 0402 (1005 Metric); Manufacturer: YAGEO; Manufacturer Part Number: CC0402KRX7R9BB221; Part Number: CC0402KRX7R9BB221; Part type: Ceramic; Tolerance: 10%; Voltage: 50V; Datasheet: https://www.yageo.com/upload/media/product/productsearch/datasheet/mlcc/UPY-GPHC_X7R_6.3V-to-250V_24.pdf
C345 = CAPACITOR_POL: 100 µF 25 V Aluminum - Polymer Capacitors Radial, Can - SMD 24mOhm 5000 Hrs @ 105°C; Manufacturer: Panasonic Electronic Components; Manufacturer Part Number: 25SVPF100M; Part Number: 25SVPF100M; Part type: Aluminum; Tolerance: 20%; Voltage: 25V; Datasheet: https://industrial.panasonic.com/cdbs/www-data/pdf/AAB8000/AAB8000C177.pdf
C298 C299 C306-C309 C346 C347 = CAP_NP: 0.1 µF ±10% 16V Ceramic Capacitor X7R 0402 (1005 Metric); Manufacturer: Yageo; Manufacturer Part Number: CC0402KRX7R7BB104; Part Number: CC0402KRX7R7BB104; Part type: Ceramic; Tolerance: 10%; Voltage: 16V; Datasheet: https://www.yageo.com/upload/media/product/app/datasheet/mlcc/upy-gphc_x7r_6_3v-to-250v.pdf
C356 C357 = CAP_NP: 0.022 µF ±10% 50V Ceramic Capacitor X7R 0402 (1005 Metric); Manufacturer: Yageo; Manufacturer Part Number: CC0402KRX7R9BB223; Part Number: CC0402KRX7R9BB223; Part type: Ceramic; Tolerance: 10%; Voltage: 50V; Datasheet: https://www.digikey.com/en/htmldatasheets/production/4954974/0/0/1/cc1206jrnpo9bn150.html?site=US&lang=en&cur=USD
J23 = 12401826E412A: USB-C (USB TYPE-C) USB 3.2 Gen 2 (USB 3.1 Gen 2, Superspeed + (USB 3.1)) Receptacle Connector 24 Position Surface Mount, Right Angle; Through Hole; Manufacturer: Amphenol Interconnect Products Corporation; Part Type: Connector; Datasheet: https://cdn.amphenol-cs.com/media/wysiwyg/files/documentation/datasheet/inputoutput/io_usb_type_c.pdf
J24 = TSM-105-01-F-SV: Connector Header Surface Mount 5 position 0.100" (2.54mm); Manufacturer: Samtec Inc.; Part Type: Connector; Datasheet: https://mm.digikey.com/Volume0/opasdata/d220001/medias/docus/6129/tsm-1xx-xx-xxx-sv-xx-xxx-x-xx-mkt.pdf
L1-L4 = INDUCTOR: 4.7 µH Shielded Molded Inductor 6.5 A 33mOhm Max Nonstandard; Current: 6.5A; DCR: 33 mOhm; Manufacturer: ECS Inc.; Manufacturer Part Number: ECS-MPIL0630-4R7MC; Part Number: ECS-MPIL0630-4R7MC; Datasheet: https://ecsxtal.com/store/pdf/ECS-MPIL0630-SMD-POWER-INDUCTOR.pdf
LB38 LB39 = LB_Inductor: 220 Ohms @ 100 MHz 1 Power Line Ferrite Bead 0603 (1608 Metric) 2.2A 50mOhm; Current: 2.2A; DCR: 50mohm; Manufacturer: Murata Electronics
Q3 = AONR21321: MOSFET P-CH 30V 24A 8DFN; Manufacturer: Alpha and Omega Semiconductor Incorporated; Part Type: MOSFET P-CH; Datasheet: https://www.aosmd.com/res/datasheets/AONR21321.pdf
R82 R197 = R: RES 0402 21.5kohm 1% 62.5mW; Manufacturer: Vishay Americas Inc.; Manufacturer Part Number: CRCW040221K5FKED; Part Number: CRCW040221K5FKED; Part type: Thick Film; Power: 62.5mW; Tolerance: 1%
R86 R92 = R: 61.9 kOhms ±1% 0.063W, 1/16W Chip Resistor 0402 (1005 Metric) Moisture Resistant Thick Film; Manufacturer: Yageo; Manufacturer Part Number: RC0402FR-0761K9L; Part Number: RC0402FR-0761K9L; Part type: Thick Film; Power: 1/16W; Tolerance: 1%; Datasheet: https://www.yageo.com/upload/media/product/products/datasheet/rchip/PYu-RC_Group_51_RoHS_L_12.pdf
R87 = R: 24.3 kOhms ±1% 0.063W, 1/16W Chip Resistor 0402 (1005 Metric) Moisture Resistant Thick Film; Manufacturer: Yageo; Manufacturer Part Number: RC0402FR-1324K3L; Part Number: RC0402FR-1324K3L; Part type: Thick Film; Power: 1/16W; Tolerance: 1%; Datasheet: https://www.yageo.com/upload/media/product/products/datasheet/rchip/PYu-RC_Group_51_RoHS_L_12.pdf
R187 = R: RES 0402 787kohm 1% 62.5mW; Manufacturer: KOA Speer Electronics, Inc.; Manufacturer Part Number: RK73H1ETTP7873F; Part Number: RK73H1ETTP7873F; Part type: Thick Film; Power: 62.5mW; Tolerance: 1%
R91 R100 R103 R188 = R: 10 Ohms ±1% 0.125W, 1/8W Chip Resistor 0402 (1005 Metric) Moisture Resistant Thick Film; Manufacturer: Yageo; Manufacturer Part Number: RC0402FR-7W10RL; Part Number: RC0402FR-7W10RL; Part type: Thick Film; Power: 1/8W; Tolerance: 1%; Datasheet: https://www.yageo.com/upload/media/product/products/datasheet/rchip/PYu-RC_Group_51_RoHS_L_12.pdf
R189 R198 = R: 432 kOhms ±1% 0.063W, 1/16W Chip Resistor 0402 (1005 Metric) Moisture Resistant Thick Film; Manufacturer: Yageo; Manufacturer Part Number: RC0402FR-07432KL; Part Number: RC0402FR-07432KL; Part type: Thick Film; Power: 1/16W; Tolerance: 1%; Datasheet: https://www.yageo.com/upload/media/product/products/datasheet/rchip/PYu-RC_Group_51_RoHS_L_12.pdf
R190 = R: RES 0402 39.2kohm 1% 62.5mW; Manufacturer: NIC COMPONENTS CORP.; Manufacturer Part Number: NRC04F3922TRF; Part Number: NRC04F3922TRF; Part type: Thick Film; Power: 62.5mW; Tolerance: 1%
R201 R202 = R: 5.1 kOhms ±1% 0.063W, 1/16W Chip Resistor 0402 (1005 Metric) Moisture Resistant Thick Film; Manufacturer: Yageo; Manufacturer Part Number: RC0402FR-075K1L; Part Number: RC0402FR-075K1L; Part type: Thick Film; Power: 1/16W; Tolerance: 1%; Datasheet: https://www.yageo.com/upload/media/product/products/datasheet/rchip/PYu-RC_Group_51_RoHS_L_12.pdf
R283 = R: RES 0402 20kohm 1% 62.5mW; Manufacturer: KOA Speer Electronics, Inc.; Manufacturer Part Number: RK73H1ETTP2002F; Part Number: RK73H1ETTP2002F; Part type: Thick Film; Power: 62.5mW; Tolerance: 01%
U4 = GS7615STDE-R_0
U10 = TLV70450DBV: Linear Voltage Regulator IC Positive Fixed 1 Output 150mA SOT-23-5; Manufacturer: Texas Instruments; Manufacturer Part Number: TLV70450DBVR; Part Number: TLV70450DBVR; Part Type: Regulator; Datasheet: https://www.ti.com/lit/ds/symlink/tlv704.pdf
U11 = GS7155NVTD-R_0
U13 U16 U17 = NCP114AMX180TCG: Linear Voltage Regulator IC Positive Fixed 1 Output 300mA 4-UDFN (1.0x1.0); Manufacturer: onsemi; Part Type: Regulator; Datasheet: https://www.onsemi.com/pdf/datasheet/ncp114-d.pdf
U19 = TPS22965NDSGR
U22 = MP28167-A: Buck-Boost Switching Regulator IC Positive Adjustable 1V 1 Output 3A 16-PowerVFQFN; Manufacturer: Monolithic Power Systems, Inc.; Part Type: Regulator; Datasheet: https://www.monolithicpower.com/en/documentview/productdocument/index/version/2/document_type/Datasheet/lang/en/sku/MP28167GQ-A/document_id/9621/
U23 = STUSB4500: USB Controller USB 2.0 I2C Interface 24-QFN (4x4); Manufacturer: STMicroelectronics; Part Type: USB; Datasheet: https://www.st.com/resource/en/datasheet/stusb4500.pdf
C300-C303 C310-C317 = CAP_NP: 22 µF ±20% 10V Ceramic Capacitor X5R 0603 (1608 Metric); Manufacturer: Murata; Manufacturer Part Number: GRM188R61A226ME15D; Part Number: GRM188R61A226ME15D; Part type: Ceramic; Tolerance: 20%; Voltage: 10V; Datasheet: https://search.murata.co.jp/Ceramy/image/img/A01X/G101/ENG/GRM188R61A226ME15-01.pdf
C359 = CAP_NP: 15 pF ±2% 50V Ceramic Capacitor C0G, NP0 0402 (1005 Metric); Manufacturer: Murata Electronics; Manufacturer Part Number: GJM1555C1H150GB01D; Part Number: GJM1555C1H150GB01D; Part type: Ceramic; Tolerance: 2%; Voltage: 50V; Datasheet: https://search.murata.co.jp/Ceramy/image/img/A01X/G101/ENG/GJM1555C1H150GB01-01.pdf
C360 C361 = CAP_NP: 82 pF ±5% 50V Ceramic Capacitor C0G, NP0 0402 (1005 Metric); Manufacturer: KYOCERA AVX; Manufacturer Part Number: KGM05ACG1H820JH; Part Number: KGM05ACG1H820JH; Part type: Ceramic; Tolerance: 5%; Voltage: 50V; Datasheet: https://datasheets.kyocera-avx.com/C0GNP0-KGM.pdf
R88 R94 R95 R113 R115 R117 = R: 100 kOhms ±1% 0.063W, 1/16W Chip Resistor 0402 (1005 Metric) Moisture Resistant Thick Film; Manufacturer: Yageo; Manufacturer Part Number: RC0402FR-07100KL; Part Number: RC0402FR-07100KL; Part type: Thick Film; Power: 1/16W; Tolerance: 1%; Datasheet: https://www.yageo.com/upload/media/product/app/datasheet/rchip/pyu-rc_group_51_rohs_l.pdf
R93 = R: 20 kOhms ±1% 0.063W, 1/16W Chip Resistor 0402 (1005 Metric) Moisture Resistant Thick Film; Manufacturer: Yageo; Manufacturer Part Number: RC0402FR-0720KL; Part Number: RC0402FR-0720KL; Part type: Thick Film; Power: 1/16W; Tolerance: 1%; Datasheet: https://www.yageo.com/upload/media/product/app/datasheet/rchip/pyu-rc_group_51_rohs_l.pdf
R101 R104 = R: 147 kOhms ±1% 0.063W, 1/16W Chip Resistor 0402 (1005 Metric) Moisture Resistant Thick Film; Manufacturer: Yageo; Manufacturer Part Number: RC0402FR-07147KL; Part Number: RC0402FR-07147KL; Part type: Thick Film; Power: 1/16W; Tolerance: 1%; Datasheet: https://www.yageo.com/upload/media/product/products/datasheet/rchip/PYu-RC_Group_51_RoHS_L_12.pdf
R102 R105 = R: 619 kOhms ±1% 0.063W, 1/16W Chip Resistor 0402 (1005 Metric) Moisture Resistant Thick Film; Manufacturer: Yageo; Manufacturer Part Number: RC0402FR-07619KL; Part Number: RC0402FR-07619KL; Part type: Thick Film; Power: 1/16W; Tolerance: 1%; Datasheet: https://www.yageo.com/upload/media/product/products/datasheet/rchip/PYu-RC_Group_51_RoHS_L_12.pdf
R114 R116 R118 = R: 17.4 kOhms ±1% 0.1W, 1/10W Chip Resistor 0402 (1005 Metric) Automotive AEC-Q200 Thick Film; Manufacturer: Panasonic Electronic Components; Manufacturer Part Number: ERJ-2RKF1742X; Part Number: ERJ-2RKF1742X; Part type: Thick Film; Power: 1/16W; Tolerance: 1%; Datasheet: https://industrial.panasonic.com/cdbs/www-data/pdf/RDA0000/AOA0000C304.pdf
RS1-RS3 = R-4_TERMINAL: 10 mOhms ±1% 0.5W, 1/2W Chip Resistor Wide 1206 (3216 Metric), 0612; Manufacturer: Delta Electronics/Cyntec; Manufacturer Part Number: RLM-1632W-4F-R010-FNH; Part Number: RLM-1632W-4F-R010-FNH; Part type: Thick Film; Power: 0.5W; Tolerance: 1%; Datasheet: https://www.cyntec.com/upfile/products/download/RLM-1632W-4F.pdf
U12 U14 U15 = MP1475DJ: Buck Switching Regulator IC Positive Adjustable 0.8V 1 Output 3A SOT-23-8 Thin, TSOT-23-8; Manufacturer: Monolithic Power Systems, Inc.; Part Type: Regulator; Datasheet: https://www.monolithicpower.com/en/documentview/productdocument/index/version/2/document_type/Datasheet/lang/en/sku/MP1475/document_id/342

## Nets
GND: C225.2 C245.2 C246.2 C247.2 C248.2 C250.2 C251.2 C252.2 C253.2 C254.2 C255.2 C256.2 C257.2 C258.2 C259.2 C260.2 C261.2 C262.2 C263.2 C264.2 C265.2 C266.2 C267.2 C268.2 C269.2 C270.2 C271.2 C272.2 C273.2 C274.2 C275.2 C276.2 C277.2 C278.2 C279.2 C280.2 C281.2 C282.2 C283.2 C284.2 C285.2 C286.2 C287.2 C288.2 C291.2 C292.2 C293.2 C294.2 C296.2 C297.2 C298.2 C300.2 C301.2 C302.2 C303.2 C304.2 C306.2 C307.2 C310.2 C311.2 C312.2 C313.2 C314.2 C315.2 C316.2 C317.2 C318.2 C319.2 C320.2 C321.2 C322.2 C323.2 C334.2 C335.2 C338.2 C339.2 C340.2 C344.2 C345.2 C348.2 C349.2 C350.2 C351.2 C352.2 C353.2 C354.2 C355.2 C356.2 C357.2 C362.2 C414.2 J6.2(GND) J7.2 J10.2(GND) J22.10 J23.25(TAB) J23.26(TAB) J23.27(TAB) J23.28(TAB) J23.A1(GND_A) J23.A12(GND_A) J23.B1(GND_B) J23.B12(GND_B) J24.5 J25.2(GND) J26.2(GND) Q12.2(SOURCE) R15.2 R40.2 R41.2 R48.2 R52.1 R61.1 R62.1 R65.1 R66.1 R87.2 R93.2 R102.2 R105.2 R114.2 R116.2 R118.2 R135.2 R143.2 R154.2 R171.1 R172.1 R190.2 R195.2 R196.1 R197.1 R201.1 R202.1 R203.1 S2.1 S2.4 TP21.1(TP) U4.2(GND) U5.1(GND) U5.9(GND_2) U5.13(GND_3) U6.25(EPAD) U7.2(1DIR) U7.3(2DIR) U7.4(2OE*) U7.8(GND) U7.9(GND) U7.15(1OE*) U8.2(GND) U8.5(DIR) U10.1(GND) U11.11(GND) U12.4(GND) U13.2(GND) U13.5(NC/TP) U14.4(GND) U15.4(GND) U16.2(GND) U16.5(NC/TP) U17.2(GND) U17.5(NC/TP) U19.5(GND) U19.9(EP) U22.2(GND1) U22.10(AGND) U22.11(GND2) U23.10(GND) U23.12(ADDR0) U23.13(ADDR1) U23.25(EPAD) Y2.2(GND) Y2.4(GND) ; also on sheet 4 5 6 7 8 9 10 11 12 13 14 15
VDD_1V0: J14.1 RS2.3(I2) RS2.4(V2) ; also on sheet 8 11
VDD_1V0_LDO: C321.1 U13.1(OUT) ; also on sheet 7 10
VDD_1V8: C246.1 C284.1 C285.1 C334.1 J15.1 LB29.1 LB30.1 LB31.2 LB32.2 LB33.2 LB34.2 LB35.2 LB36.2 LB37.2 Q1.2(G1) Q1.5(G2) R44.1 R46.2 R47.2 R71.2 R72.2 R80.1 R145.2 R164.1 R186.1 RS3.3(I2) RS3.4(V2) U7.1(VCCA) U8.6(VCCb) U19.1(VIN) U19.2(VIN) ; also on sheet 4 5 6 9 10 11 13 14
VDD_1V8_CAM: C335.1 R145.1 U19.7(VOUT) U19.8(VOUT) ; also on sheet 6 12
VDD_1V8_LDO: C322.1 U16.1(OUT) ; also on sheet 6 7 8 10
VDD_1V8_SYNTH: C253.1 C254.1 C255.1 LB30.2 U6.10(VDD)
VDD_2V5_LDO: C323.1 U17.1(OUT) ; also on sheet 7
VDD_2V8_LDO: C296.1 R85.2 R134.1 U11.1(VOUT) U11.2(VOUT) U11.3(VOUT) ; also on sheet 12
VDD_3V3: C225.1 C245.1 C286.1 C287.1 C294.1 C318.1 C319.1 C320.1 J13.1 J22.7 LB28.1 R17.2 R42.1 R43.1 R73.1 R74.1 R75.1 R76.1 R77.1 R78.1 R79.1 R121.2 R122.2 R123.2 R173.1 R191.2 R192.2 R193.2 R194.2 RS1.3(I2) RS1.4(V2) U4.5(IN) U7.16(VCCB) U8.1(VCCa) U11.7(VIN) U11.8(VIN) U11.9(VIN) U13.4(IN) U16.4(IN) U17.4(IN) ; also on sheet 4 6 9 13 14 15
VDD_3V3_CAM: C414.1 R17.1 U4.1(OUT) ; also on sheet 12
VDD_3V3_MCLK_BUF: C247.1 C250.1 LB28.2 U5.3(VDD)
VDD_5V0_LDO: C293.1 U10.3(OUT) U11.10(VCTL) U19.4(VBIAS)
VDD_12V: C291.1 C292.1 C297.1 C304.1 C348.1 C349.1 C350.1 C351.1 C352.1 R113.1 R115.1 R117.1 R188.2 U10.2(IN) U12.2(VIN) U14.2(VIN) U15.2(VIN) U22.12(OUT) ; also on sheet 13
VDDA_1V8_SYNTH: C274.1 C277.1 C280.1 R69.1 R70.1 U6.23(VDD)
VDDA_1V8_SYNTH_R: C283.1 LB37.1 R69.2 R70.2
VDDO0_1V8_SYNTH: C259.1 C263.1 C267.1 C271.1 LB34.1 U6.22(VDDO0)
VDDO1_1V8_SYNTH: C258.1 C262.1 C266.1 C270.1 LB33.1 U6.19(VDDO1)
VDDO2_1V8_SYNTH: C257.1 C261.1 C265.1 C269.1 LB32.1 U6.16(VDDO2)
VDDO3_1V8_SYNTH: C256.1 C260.1 C264.1 C268.1 LB31.1 U6.13(VDDO3)
VDDO_1V8_MCLK_BUF: C248.1 C251.1 C252.1 LB29.2 U5.11(VDDO) U5.15(VDDO)
VDDREF_1V8_SYNTH: C272.1 C275.1 C278.1 R67.1 U6.4(VDDREF)
VDDREF_1V8_SYNTH_R: C281.1 LB35.1 R67.2
VDDXO_1V8_SYNTH: C273.1 C276.1 C279.1 R68.1 U6.3(VDDXO)
VDDXO_1V8_SYNTH_R: C282.1 LB36.1 R68.2
BODE_PS_1V0: R100.2 R101.1 R207.2
BODE_PS_1V8: R103.2 R104.1 R208.2
BODE_PS_3V3: R91.2 R92.1 R206.2
BOOT_PS_1V0: R98.1 U14.5(BOOT)
BOOT_PS_1V8: R99.1 U15.5(BOOT)
BOOT_PS_3V3: R90.1 U12.5(BOOT)
BOOT_RC_PS_1V0: C308.1 R98.2
BOOT_RC_PS_1V8: C309.1 R99.2
BOOT_RC_PS_3V3: C299.1 R90.2
CAM_1V8_CT: C338.1 U19.6(CT)
CAM_MCLK_0: R49.1 ; also on sheet 12
CAM_MCLK_0_R: R49.2 U5.16(Q0)
CAM_MCLK_1: R51.1 ; also on sheet 12
CAM_MCLK_1_R: R51.2 U5.14(Q1)
CAM_MCLK_2: R50.1 ; also on sheet 12
CAM_MCLK_2_R: R50.2 U5.12(Q2)
CAM_MCLK_3_R: R52.2 U5.10(Q3)
CAM_MCLK_N: R39.2 R41.1 R58.2 U5.6(CLKN)
CAM_MCLK_P: R39.1 R40.1 R54.2 U5.5(CLK)
CAM_MCLK_R_N: R58.1 U6.17(OUT1*)
CAM_MCLK_R_P: R54.1 U6.18(OUT1)
CLK_SYNTH_EXTIN_N: J26.1 U6.6(CLKIN*)
CLK_SYNTH_EXTIN_P: J25.1 U6.5(CLKIN)
CLK_SYNTH_LOCK: U6.24(LOCK) ; also on sheet 4
CLK_SYNTH_OE: R48.1 U6.7(OE_NCS) ; also on sheet 4
CLNK_JTAG_BYPASS: R177.1 R179.1
CLNK_JTAG_TDI: R178.2 ; also on sheet 9
CLNK_JTAG_TDO: R163.1 ; also on sheet 9
CPRO_CAM_1V8_EN: R143.1 U19.3(ON) ; also on sheet 4
CPRO_CAM_2V8_EN: R135.1 U11.6(EN) ; also on sheet 4
CPRO_CAM_3V3_EN: R15.1 U4.4(EN/EN*) ; also on sheet 4
CPRO_CTRL_I2C_SCL: R47.1 U6.8(SCL/SCLK) ; also on sheet 4
CPRO_CTRL_I2C_SDA: R46.1 U6.9(SDA/SDIO) ; also on sheet 4
CPRO_JESD_REFCLK_N: R57.2 R65.2 ; also on sheet 7
CPRO_JESD_REFCLK_P: R53.2 R66.2 ; also on sheet 7
CPRO_JESD_REFCLK_R_N: R57.1 U6.21(OUT0*)
CPRO_JESD_REFCLK_R_P: R53.1 U6.20(OUT0)
CPRO_JTAG_BYPASS: R174.1 R176.1
CPRO_JTAG_TDI: R175.2 ; also on sheet 4
CPRO_JTAG_TDO: R157.1 ; also on sheet 4
CPRO_JTAG_THRU: R157.2 R176.2 R177.2 R178.1
CPRO_MCLK_BUF_OE_3V3: Q12.3(DRAIN) R173.2 U5.2(OE)
CPRO_MCLK_BUF_OE_N: Q12.1(GATE) R44.2 ; also on sheet 4
EN_PS_1V0: R115.2 R116.1 U14.6(EN/FSYNC)
EN_PS_1V0_LDO: R123.1 U13.3(EN)
EN_PS_1V8: R117.2 R118.1 R119.2 U15.6(EN/FSYNC)
EN_PS_1V8_LDO: R121.1 U16.3(EN)
EN_PS_2V5_LDO: R122.1 U17.3(EN)
EN_PS_3V3: R113.2 R114.1 R120.2 U12.6(EN/FSYNC)
FB_PS_1V0: R96.1 U14.8(FB)
FB_PS_1V8: R97.1 U15.8(FB)
FB_PS_3V3: R89.1 U12.8(FB)
FB_R_PS_1V0: C360.2 R96.2 R101.2 R102.1
FB_R_PS_1V8: C361.2 R97.2 R104.2 R105.1
FB_R_PS_3V3: C359.2 R89.2 R92.2 R93.1
FMC_CLK2_C2M_N: R60.2 R171.2 ; also on sheet 13
FMC_CLK2_C2M_P: R56.2 R172.2 ; also on sheet 13
FMC_CLK2_C2M_R_N: R60.1 U6.11(OUT3*)
FMC_CLK2_C2M_R_P: R56.1 U6.12(OUT3)
FPGA_JTAG_EN: J7.1 R80.2 ; also on sheet 4 9
FPGA_JTAG_TCLK: R168.1 ; also on sheet 4 9
FPGA_JTAG_TCLK_3V3: J22.4 R162.2
FPGA_JTAG_TCLK_3V3_R: R78.2 R162.1 U7.11(2B1)
FPGA_JTAG_TCLK_R: R168.2 U7.6(2A1)
FPGA_JTAG_TMS: U7.5(1A2) ; also on sheet 4 9
FPGA_JTAG_TMS_3V3: J22.2 R77.2 U7.12(1B2)
FPGA_PROG_I2C_SCL: Q1.1(S1) R72.1 ; also on sheet 4 9
FPGA_PROG_I2C_SCL_3V3: J22.5 Q1.6(D1) R73.2
FPGA_PROG_I2C_SDA: Q1.4(S2) R71.1 ; also on sheet 4 9
FPGA_PROG_I2C_SDA_3V3: J22.1 J22.3 Q1.3(D2) R74.2
FPGA_PROGRAM_N: R186.2 S1.1 S1.4 ; also on sheet 4 9
FPGA_PROGRAM_N_PD: R154.1 S1.2 S1.3
FPGA_RESET_N: R164.2 S2.2 S2.3 ; also on sheet 4 9
HFCOMP_PS_1V0: C360.1 R207.1
HFCOMP_PS_1V8: C361.1 R208.1
HFCOMP_PS_3V3: C359.1 R206.1
JTAG_LS_UNUSED_IN: R76.2 U7.13(1B1)
MCLK_BUF_EN: R42.2 U5.4(CLK_EN)
MCLK_BUF_SEL: R43.2 U5.7(CLK_SEL)
PG_PS_1V0: R94.1 R119.1 U14.1(MOD/PG/AGND)
PG_PS_1V8: R95.1 R120.1 U15.1(MOD/PG/AGND)
PG_PS_2V8_LDO: R134.2 U11.5(POK)
PG_PS_3V3: R88.1 U12.1(MOD/PG/AGND) ; also on sheet 14
PROBE_JTAG_TDI: R174.2 R175.1 U7.7(2A2)
PROBE_JTAG_TDI_3V3: J22.6 R79.2 U7.10(2B2)
PROBE_JTAG_TDO: R163.2 R179.2 U8.4(B)
PROBE_JTAG_TDO_3V3: J22.8 R75.2 U8.3(A)
PS_2V8_BD: R84.1 R85.1 R86.1
PS_2V8_FB: C295.2 R86.2 R87.1 U11.4(FB)
PS_2V8_MID: C295.1 R84.2
PS_12V_BODE: R188.1 R189.1
PS_12V_BST1: C346.1 U22.16(BST1)
PS_12V_BST2: C347.2 U22.13(BST2)
PS_12V_FB: R187.2 U22.8(FB)
PS_12V_OC: C356.1 R197.2 U22.7(OC/ADD)
PS_12V_SW1: C346.2 L4.2 U22.15(SW1)
PS_12V_SW2: C347.1 L4.1 U22.14(SW2)
PS_12V_VCC_3V6: C355.1 U22.9(VCC)
PWR_I2C_MP28167_INT: J24.3 R193.1 U22.4(ALT)
PWR_I2C_SCL: J24.1 R191.1 U22.5(SCL) U23.7(SCL)
PWR_I2C_SDA: J24.2 R192.1 U22.6(SDA) U23.8(SDA)
PWR_I2C_STUSB4500_INT: J24.4 R194.1 U23.19(ALERT)
REFCLK_SMP_N: J10.1 R59.2 R61.2
REFCLK_SMP_P: J6.1 R55.2 R62.2
REFCLK_SMP_R_N: R59.1 U6.14(OUT2*)
REFCLK_SMP_R_P: R55.1 U6.15(OUT2)
SNN_CAM_3V3_OC_N: U4.3(OC*/ISET)
SNN_CLKBUF_8: U5.8(LVCMOS_CLK)
SNN_FPGA_JTAG_HDR: J22.9
SNN_PS_5V0_4: U10.4(NC)
SNN_USBC_D1N: J23.A7(D1_N)
SNN_USBC_D1P: J23.A6(D1_P)
SNN_USBC_D2N: J23.B7(D2_N)
SNN_USBC_D2P: J23.B6(D2_P)
SNN_USBC_PD_A_B_SIDE: U23.17(A_B_SIDE)
SNN_USBC_PD_ATTACH: U23.11(ATTACH)
SNN_USBC_PD_GPIO: U23.15(GPIO)
SNN_USBC_PD_NC: U23.3(NC)
SNN_USBC_PD_POK2: U23.20(POWER_OK2)
SNN_USBC_PD_POK3: U23.14(POWER_OK3)
SNN_USBC_RX1N: J23.B10(RX1_N)
SNN_USBC_RX1P: J23.B11(RX1_P)
SNN_USBC_RX2N: J23.A10(RX2_N)
SNN_USBC_RX2P: J23.A11(RX2_P)
SNN_USBC_SBU1: J23.A8(SBU1)
SNN_USBC_SBU2: C289.1 C362.1 J23.A4(VBUS_A) J23.A9(VBUS_A) J23.B4(VBUS_B) J23.B9(SBU2) Q3.1(S) Q3.2(S) Q3.3(S) R200.1 R283.1 U23.24(VDD)
SNN_USBC_TX1N: J23.A3(TX1_N)
SNN_USBC_TX1P: J23.A2(TX1_P)
SNN_USBC_TX2N: J23.B3(TX2_N)
SNN_USBC_TX2P: J23.B2(TX2_P)
SW_PS_1V0: C308.2 L2.1 U14.3(SW)
SW_PS_1V8: C309.2 L3.1 U15.3(SW)
SW_PS_3V3: C299.2 L1.1 U12.3(SW)
USBC_CC1: J23.A5(CC1) R201.2 U23.1(CC1DB) U23.2(CC1)
USBC_CC2: J23.B5(CC2) R202.2 U23.4(CC2) U23.5(CC2DB)
USBC_PD_1V2: C353.1 U23.21(VREG_1V2)
USBC_PD_2V7: C354.1 U23.23(VREG_2V7)
USBC_PD_RESET: R196.2 U23.6(RESET)
USBC_PD_VBUS_DISCH: R200.2 U23.18(VBUS_VS_DISCH)
USBC_PD_VBUS_EN_SNK: R82.2 R203.2 U23.16(VBUS_EN_SNK)
USBC_PD_VSYS: R195.1 U23.22(VSYS)
USBC_SNK: C288.1 C344.1 C345.1 LB38.1 LB39.1 R198.1 R199.1 U22.1(VIN)
USBC_SNK_SS: C339.1 C340.1 LB38.2 LB39.2 Q3.5(D)
USBC_SNK_SS_G: C289.2 Q3.4(G) R82.1 R283.2
VBIAS_PS_1V0: C306.1 R94.2 U14.7(VCC)
VBIAS_PS_1V8: C307.1 R95.2 U15.7(VCC)
VBIAS_PS_3V3: C298.1 R88.2 U12.7(VCC)
VOUT_PS_1V0: C310.1 C312.1 C314.1 C316.1 J14.2 L2.2 R100.1 RS2.1(V1) RS2.2(I1)
VOUT_PS_1V8: C311.1 C313.1 C315.1 C317.1 J15.2 L3.2 R103.1 RS3.1(V1) RS3.2(I1)
VOUT_PS_3V3: C300.1 C301.1 C302.1 C303.1 J13.2 L1.2 R91.1 RS1.1(V1) RS1.2(I1)
XIN_SYNTH: U6.1(XIN/REF) Y2.1(Crystal)
XOUT_SYNTH: U6.2(XOUT) Y2.3(Crystal)
N21116737: C357.1 R198.2 U22.3(EN)
N21124808: R187.1 R189.2 R190.1
N21141537: R199.2 U23.9(DISCH)

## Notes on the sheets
sheet 16
- Clock
- I/O Standard
- CPRO_JESD_REFCLK
- HCSL
- CAM_MCLK
- LVDS
- REFCLK_SMP
- HCSL
- FMC_CLK2_C2M
- LVDS
- I2C 7-bit address = 0x09
sheet 17
- JTAG Chain
- 1
- 2
- 3
- 4
- CertusPro-NX100
- CrossLink-NX17
- TDI
- TDO
- TDI
- TDO
- 5
- 6
- 7
- 8
- 9
- 10
- Programming Cable Mapping
- FPGA
- FTDI C232HM-DDHSL-0 JTAG
- FTDI C232HM-DDHSL-0 I2C
- LATTICE HW-USBN-2B
- FPGA PROG_I2C_SDA
- DNC
- FTDI SDA IN               GREEN
- DNC
- FPGA TMS
- FTDI TMS        BROWN
- DNC
- TMS                  PURPLE
- 1
- 2
- FPGA PROG_I2C_SDA
- DNC
- FTDI SDA OUT             YELLOW
- I2C SDA              GREEN/WHITE
- FPGA TCK
- FTDI TCK         ORANGE
- DNC
- TCK                  WHITE
- 3
- 4
- FPGA PROG_I2C_SCL
- DNC
- FTDI SCL                 ORANGE
- I2C SCL             YELLOW/WHITE
- FPGA TDI
- FTDI TDI        YELLOW
- DNC
- TDI                  ORANGE
- 5
- 6
- 3.3V
- DNC
- DNC
- VCC                   RED
- FPGA TDO
- FTDI TDO         GREEN
- DNC
- TDO                   BROWN
- 7
- 8
- NC
- DNC
- DNC
- DNC
- GND
- GND            BLACK
- GND                   BLACK
- GND                   BLACK
- 9
- 10
sheet 18
- MP1475
  Vout = 0.807*(1+Rt/Rb)
  Vout = 0.807*(1+61.9k/20k)
  Vout = 3.304V
  MP2325
  Vout = 0.791*(1+Rt/Rb)
  Vout = 0.791*(1+60.4k/18.7k)
  Vout = 3.346V
- MP1475
  Vout = 0.807*(1+Rt/Rb)
  Vout = 0.807*(1+147k/619k)
  Vout = 0.999V
  MP2325
  Vout = 0.791*(1+Rt/Rb)
  Vout = 0.791*(1+110k/422k)
  Vout = 0.997V
- MP1475
  Vout = 0.807*(1+Rt/Rb)
  Vout = 0.807*(1+147k/118k)
  Vout = 1.812V
  MP2325
  Vout = 0.791*(1+Rt/Rb)
  Vout = 0.791*(1+113k/88.7k)
  Vout = 1.799V
- Vdisable_falling_max = 1.40V
  Vin = 1.40V/(17.4k/(100k+17.4k))
  Vin = 9.446V
  Venable_rising_min = 1.20V
  Vin = 1.20V/(17.4k/(100k+17.4k))
  Vin = 8.097V
- Power Sequence
sheet 19
- I2C 7-bit address = 0x28
- I2C 7-bit address = 0x60
